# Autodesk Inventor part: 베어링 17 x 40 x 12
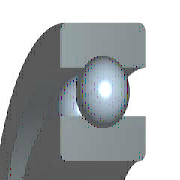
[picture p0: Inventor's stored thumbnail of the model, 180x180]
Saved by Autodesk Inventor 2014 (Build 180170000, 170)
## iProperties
IsCustomPart: 1
Created: 2012-02
Part Number: 베어링 17 x 40 x 12
Material: 강철, 연강
Description: 깊은 그루브 볼 베어링
Document SubType Name: Modeling
Standard: KS B 2023
Designer: mduedu
Standards Organization: KS
Language: ko-KR
Size Designation: 6203 - 17 x 40 x 12
Categories: <MemberInstance><Categories><Category DisplayName="샤프트 부품" InternalName="7f7aeb1f-a693-4053-b835-cee3144e0d98" Mnemonic="SHFT"><Category DisplayName="베어링" Inter
Density: 1 g/cm^3
Appearance: Yellow
Author: mduedu
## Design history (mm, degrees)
sketch "스케치" dims "d0" = 5.98 (= -0.26 x WD + 0.26 x BD)
  geometry: L1 (3.01, 14.25)-(8.99, 14.25); L2 (6, 14.25)-(6, 11.26); L3 (6, 14.25)-(6, 17.24); L4 (3.778, 12.249)-(0, 12.249); L5 (0, 8.5)-(12, 8.5); L6 (3.778, 16.251)-(0, 16.251); L7 (0, 20)-(12, 20); L8 (12, 8.5)-(12, 12.249); L9 (8.222, 12.249)-(12, 12.249); L10 (8.222, 16.251)-(12, 16.251); L11 (12, 20)-(12, 16.251); L12 (-1.4, 0)-(8.4, 0) reference; L13 (0, -0.3)-(0, 5.3) reference
  constraints: 22 end point, 4 point on line, 2 collinear, 2 perpendicular, 2 symmetric about line, 1 midpoint, 1 parallel, 14 other
  dimensions: "d9" = 17 diameter of L5 L12 (= WD); "d11" = 40 diameter of L7 L12 (= BD); "d12" = 12 distance between parallel lines of L8 L13 (= KB); "d13" = 24.498 diameter of L9 L12 (= 0.326 x BD + 0.674 x WD)
revolve "본체" stored, may be unused: angle "d6" = 90 deg
revolve "볼" stored, may be unused: angle "d7" = 90 deg
pattern_circular "IDS_ARRAYBALL[SIMPL:T]" dims angle "d3" = 360 deg
body "Solid1"
fillet "모깎기1" dims "d1" = 0.6 (= KRS)
other parameters: "WD" = 17 [user parameter; used in 5 equation terms], "BD" = 40 [user parameter; used in 5 equation terms], "KB" = 12 [user parameter; used in 1 equation term], "KRS" = 0.6 [user parameter; used in 1 equation term], "d4" = 0, "d5" = 0, "d8" = 0, "d14" = 0, "d15" = 0, "BBA" = 0 [user parameter], "BC0" = 4750000 [user parameter], "BC" = 9560000 [user parameter], "WR" = 8.5 (= 0.5 x WD) [user parameter]
